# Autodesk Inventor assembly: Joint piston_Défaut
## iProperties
Shininess: 64.0
Length Units: 11269
Angle Units: 11279
Time Units: 11290
Mass Units: 11283
Length Display Precision: 3
Angle Display Precision: 2
Compacted: True
Created: 2006-01
Part Number: Joint piston_Défaut
Document SubType Name: Assembly
Designer: riri
Density: 0.0
Volumn: 0.0
Area: 0.0
PropertySet Name: Model Information
Control State: 0
Master: False
Checked Out: False
Author: riri
